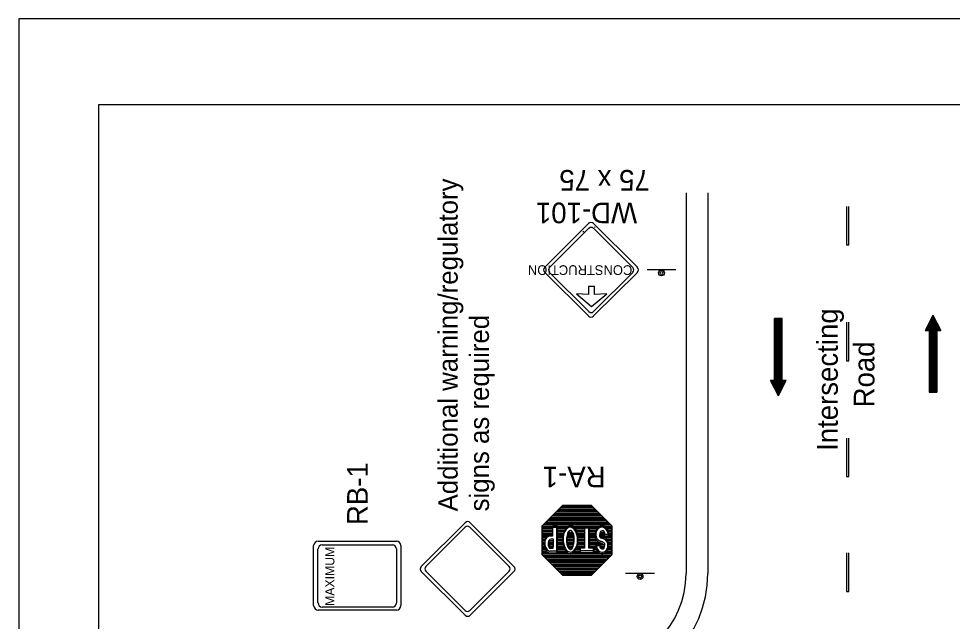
# Model space of a CAD drawing. Extents: x 1833 to 2049, y 205 to 484.
# Drawn here: x 1833.5 to 1950.4, y 408.9 to 484.4 of the extents above; entities that cross this region are included whole.
import ezdxf

# ---------------------------------------------------------------- set-up
doc = ezdxf.new("R2010")
doc.units = 0
for name, color, linetype in [('Level 10', 7, 'Continuous'), ('Level 2', 7, 'Continuous'), ('Level 44', 7, 'Continuous'), ('Level 60', 7, 'Continuous')]:
    doc.layers.add(name, color=color, linetype=linetype)

msp = doc.modelspace()

# ---------------------------------------------------------------- linework, layer by layer
at = {"layer": 'Level 10'}
for p, q in [((1917.06, 462.56), (1917.06, 414.87)), ((1919.79, 462.56), (1919.79, 414.87)), ((1928.14, 439.06), (1928.14, 446.8)), ((1929.11, 446.8), (1928.14, 446.8)), ((1928.14, 438.09), (1928.14, 446.8)), ((1928.27, 437.85), (1928.27, 446.8)), ((1928.39, 437.61), (1928.39, 446.8)), ((1928.51, 437.36), (1928.51, 446.8)), ((1928.63, 437.12), (1928.63, 446.8)), ((1928.75, 437.36), (1928.75, 446.8)), ((1928.87, 437.61), (1928.87, 446.8)), ((1928.99, 437.85), (1928.99, 446.8)), ((1929.11, 439.06), (1929.11, 446.8)), ((1929.11, 438.09), (1929.11, 446.8)), ((1947.99, 447.25), (1947.03, 445.31)), ((1947.87, 447), (1947.87, 437.57)), ((1947.99, 447.25), (1947.99, 437.57)), ((1947.99, 447.25), (1948.96, 445.31)), ((1948.11, 447), (1948.11, 437.57)), ((1947.27, 445.79), (1947.27, 445.31)), ((1947.39, 446.04), (1947.39, 445.31)), ((1947.51, 446.28), (1947.51, 437.57)), ((1947.63, 446.52), (1947.63, 437.57)), ((1947.75, 446.76), (1947.75, 437.57)), ((1948.23, 446.76), (1948.23, 437.57)), ((1948.36, 446.52), (1948.36, 437.57)), ((1948.48, 446.28), (1948.48, 437.57)), ((1948.6, 446.04), (1948.6, 445.31)), ((1948.72, 445.79), (1948.72, 445.31)), ((1947.03, 445.31), (1947.51, 445.31)), ((1947.14, 445.55), (1947.14, 445.31)), ((1947.51, 445.31), (1947.51, 437.57)), ((1948.48, 445.31), (1948.48, 437.57)), ((1948.48, 445.31), (1948.96, 445.31)), ((1948.84, 445.55), (1948.84, 445.31)), ((1928.63, 437.12), (1927.66, 439.06)), ((1928.14, 439.06), (1927.66, 439.06)), ((1927.78, 438.81), (1927.78, 439.06)), ((1927.9, 438.57), (1927.9, 439.06)), ((1928.02, 438.33), (1928.02, 439.06)), ((1928.63, 437.12), (1929.6, 439.06)), ((1929.6, 439.06), (1929.11, 439.06)), ((1929.23, 438.33), (1929.23, 439.06)), ((1929.35, 438.57), (1929.35, 439.06)), ((1929.48, 438.81), (1929.48, 439.06)), ((1947.51, 437.57), (1948.48, 437.57))]:
    msp.add_line(p, q, dxfattribs=at)
for radius in [14.52, 11.79]:
    msp.add_arc((1905.27, 414.87), radius, 270, 0, dxfattribs=at)
at = {"layer": 'Level 2'}
for p, q in [((1937.18, 460.87), (1937.18, 456.03)), ((1937.47, 456.03), (1937.47, 460.87)), ((1904.14, 457.65), (1904.24, 457.76)), ((1905.59, 458.22), (1905.69, 458.32)), ((1937.18, 456.03), (1937.47, 456.03)), ((1937.18, 446.36), (1937.18, 441.52)), ((1937.47, 441.52), (1937.47, 446.36)), ((1937.18, 441.52), (1937.47, 441.52)), ((1937.18, 431.84), (1937.18, 427.01)), ((1937.47, 427.01), (1937.47, 431.84)), ((1937.18, 427.01), (1937.47, 427.01)), ((1937.18, 417.45), (1937.18, 412.61)), ((1937.47, 412.61), (1937.47, 417.45)), ((1937.18, 412.61), (1937.47, 412.61))]:
    msp.add_line(p, q, dxfattribs=at)
at = {"layer": 'Level 44'}
for p, q in [((1904.83, 458.73), (1899.36, 453.25)), ((1910.96, 453.25), (1905.48, 458.73)), ((1899.97, 453.19), (1904.89, 458.12)), ((1905.48, 458.12), (1910.41, 453.19)), ((1910.95, 453.25), (1910.96, 453.25)), ((1915.8, 452.93), (1912.17, 452.93)), ((1899.36, 452.6), (1904.83, 447.13)), ((1904.89, 447.68), (1899.97, 452.6)), ((1905.48, 447.13), (1910.96, 452.6)), ((1910.41, 452.6), (1905.48, 447.68)), ((1905.61, 450.84), (1904.86, 450.84)), ((1904.86, 450.84), (1904.86, 449.83)), ((1905.61, 449.83), (1905.61, 450.84)), ((1904.86, 449.83), (1903.35, 449.91)), ((1903.35, 449.91), (1905.23, 448.32)), ((1905.23, 448.32), (1907.12, 449.91)), ((1907.12, 449.91), (1905.61, 449.83)), ((1901.6, 423.38), (1899.05, 420.83)), ((1905.23, 423.38), (1901.6, 423.38)), ((1907.78, 420.83), (1905.23, 423.38)), ((1889.38, 421.22), (1883.9, 415.75)), ((1895.5, 415.75), (1890.03, 421.22)), ((1884.45, 415.75), (1889.38, 420.67)), ((1889.97, 420.67), (1894.89, 415.75)), ((1899.05, 420.83), (1899.05, 417.2)), ((1900.88, 420.64), (1900.35, 420.64)), ((1900.35, 420.64), (1900.35, 419.55)), ((1900.39, 419.76), (1900.39, 420.85)), ((1900.39, 420.85), (1900.92, 420.85)), ((1900.88, 417.45), (1900.88, 420.64)), ((1900.92, 420.85), (1900.92, 417.66)), ((1904.89, 420.55), (1904.33, 420.55)), ((1904.33, 420.55), (1904.33, 418.05)), ((1904.38, 420.76), (1904.93, 420.76)), ((1904.38, 418.26), (1904.38, 420.76)), ((1904.89, 418.04), (1904.89, 420.55)), ((1904.93, 420.76), (1904.93, 418.25)), ((1907.24, 420.36), (1907.24, 420.36)), ((1907.78, 417.2), (1907.78, 420.83)), ((1870.99, 418.93), (1880.77, 418.93)), ((1900.35, 419.55), (1900.02, 419.55)), ((1900.39, 419.76), (1900.06, 419.76)), ((1900.41, 418.95), (1900.07, 418.95)), ((1900.41, 418.95), (1900.07, 418.95)), ((1900.08, 419.76), (1900.39, 419.76)), ((1900.46, 419.16), (1900.12, 419.16)), ((1900.46, 419.16), (1900.12, 419.16)), ((1900.41, 418.02), (1900.41, 418.95)), ((1900.41, 418.02), (1900.41, 418.95)), ((1900.46, 418.23), (1900.46, 419.16)), ((1900.46, 418.23), (1900.46, 419.16)), ((1907.35, 419.52), (1906.85, 419.52)), ((1907.4, 419.73), (1906.9, 419.73)), ((1870.41, 410.85), (1870.41, 418.35)), ((1870.95, 411.18), (1870.95, 417.93)), ((1871.47, 418.45), (1880.27, 418.45)), ((1880.79, 417.93), (1880.79, 411.18)), ((1881.35, 418.35), (1881.35, 410.85)), ((1900.92, 417.66), (1900.03, 417.66)), ((1900.07, 418.02), (1900.41, 418.02)), ((1900.07, 418.02), (1900.41, 418.02)), ((1900.11, 418.23), (1900.46, 418.23)), ((1900.11, 418.23), (1900.46, 418.23)), ((1902.62, 417.55), (1902.61, 417.55)), ((1902.64, 418.09), (1902.62, 418.09)), ((1904.33, 418.05), (1903.78, 418.05)), ((1903.78, 418.05), (1903.78, 417.48)), ((1903.82, 417.69), (1903.82, 418.26)), ((1903.82, 418.26), (1904.38, 418.26)), ((1905.52, 417.69), (1903.82, 417.69)), ((1905.47, 418.04), (1904.89, 418.04)), ((1904.93, 418.25), (1905.52, 418.25)), ((1905.47, 417.48), (1905.47, 418.04)), ((1905.52, 418.25), (1905.52, 417.69)), ((1905.74, 418.37), (1906.28, 418.37)), ((1905.78, 418.58), (1906.33, 418.58)), ((1899.05, 417.2), (1901.6, 414.65)), ((1899.99, 417.45), (1900.88, 417.45)), ((1903.78, 417.48), (1905.47, 417.48)), ((1905.23, 414.65), (1907.78, 417.2)), ((1871.24, 415.43), (1871.24, 415.43)), ((1883.9, 415.1), (1889.38, 409.62)), ((1883.91, 415.1), (1883.9, 415.1)), ((1889.38, 410.23), (1884.45, 415.16)), ((1894.89, 415.16), (1889.97, 410.23)), ((1890.03, 409.62), (1895.5, 415.1)), ((1901.6, 414.65), (1905.23, 414.65)), ((1913.12, 414.88), (1909.49, 414.88)), ((1880.27, 410.66), (1871.47, 410.66)), ((1880.27, 410.66), (1880.27, 410.66)), ((1881.11, 410.99), (1881.11, 410.99)), ((1880.77, 410.28), (1870.99, 410.28)), ((1880.77, 410.28), (1880.77, 410.28))]:
    msp.add_line(p, q, dxfattribs=at)
msp.add_lwpolyline([(1899.05, 420.83), (1901.6, 423.38), (1905.23, 423.38), (1907.78, 420.83), (1907.78, 417.2), (1905.23, 414.65), (1901.6, 414.65), (1899.05, 417.2)], close=True, dxfattribs=at)
for points in [[(1906.21, 422.39), (1900.61, 422.39)], [(1906.03, 422.57), (1900.79, 422.57)], [(1905.85, 422.75), (1900.97, 422.75)], [(1905.67, 422.94), (1901.15, 422.94)], [(1905.48, 423.12), (1901.34, 423.12)], [(1905.31, 423.3), (1901.52, 423.3)], [(1907.48, 421.12), (1899.34, 421.12)], [(1907.3, 421.3), (1899.52, 421.3)], [(1907.12, 421.49), (1899.7, 421.49)], [(1906.94, 421.67), (1899.88, 421.67)], [(1906.76, 421.85), (1900.07, 421.85)], [(1906.58, 422.03), (1900.25, 422.03)], [(1906.39, 422.21), (1900.43, 422.21)], [(1907.78, 420.76), (1899.05, 420.76)], [(1900.35, 420.58), (1899.05, 420.58)], [(1900.35, 420.4), (1899.05, 420.4)], [(1900.35, 420.21), (1899.05, 420.21)], [(1900.35, 420.03), (1899.05, 420.03)], [(1907.67, 420.94), (1899.16, 420.94)], [(1902.27, 420.58), (1900.88, 420.58)], [(1902.06, 420.4), (1900.88, 420.4)], [(1901.92, 420.21), (1900.88, 420.21)], [(1901.83, 420.03), (1900.88, 420.03)], [(1906.24, 420.58), (1902.85, 420.58)], [(1904.33, 420.4), (1903.06, 420.4)], [(1904.33, 420.21), (1903.19, 420.21)], [(1904.33, 420.03), (1903.29, 420.03)], [(1906, 420.4), (1904.89, 420.4)], [(1905.87, 420.21), (1904.89, 420.21)], [(1905.78, 420.03), (1904.89, 420.03)], [(1907.78, 420.58), (1906.8, 420.58)], [(1907.78, 420.4), (1907.01, 420.4)], [(1907.78, 420.21), (1907.15, 420.21)], [(1907.78, 420.03), (1907.24, 420.03)], [(1900.35, 419.85), (1899.05, 419.85)], [(1900.35, 419.67), (1899.05, 419.67)], [(1899.82, 419.49), (1899.05, 419.49)], [(1899.57, 419.31), (1899.05, 419.31)], [(1899.45, 419.13), (1899.05, 419.13)], [(1899.38, 418.94), (1899.05, 418.94)], [(1899.33, 418.76), (1899.05, 418.76)], [(1900.41, 418.76), (1899.83, 418.76)], [(1901.76, 419.85), (1900.88, 419.85)], [(1901.71, 419.67), (1900.88, 419.67)], [(1901.67, 419.49), (1900.88, 419.49)], [(1901.64, 419.31), (1900.88, 419.31)], [(1901.63, 419.13), (1900.88, 419.13)], [(1901.62, 418.94), (1900.88, 418.94)], [(1901.63, 418.76), (1900.88, 418.76)], [(1903.02, 419.13), (1902.08, 419.13)], [(1903.02, 418.94), (1902.08, 418.94)], [(1903.01, 418.76), (1902.08, 418.76)], [(1903, 419.31), (1902.1, 419.31)], [(1902.96, 419.49), (1902.13, 419.49)], [(1902.9, 419.67), (1902.19, 419.67)], [(1902.82, 419.85), (1902.28, 419.85)], [(1904.33, 419.85), (1903.35, 419.85)], [(1904.33, 419.67), (1903.4, 419.67)], [(1904.33, 419.49), (1903.43, 419.49)], [(1904.33, 419.31), (1903.45, 419.31)], [(1904.33, 418.76), (1903.46, 418.76)], [(1904.33, 419.13), (1903.47, 419.13)], [(1904.33, 418.94), (1903.47, 418.94)], [(1905.72, 419.85), (1904.89, 419.85)], [(1905.71, 419.67), (1904.89, 419.67)], [(1905.71, 419.49), (1904.89, 419.49)], [(1905.74, 419.31), (1904.89, 419.31)], [(1905.79, 419.13), (1904.89, 419.13)], [(1905.92, 418.94), (1904.89, 418.94)], [(1906.17, 418.76), (1904.89, 418.76)], [(1906.84, 419.67), (1906.22, 419.67)], [(1907.78, 419.49), (1906.24, 419.49)], [(1906.78, 419.85), (1906.27, 419.85)], [(1907.78, 419.31), (1906.43, 419.31)], [(1907.78, 419.13), (1906.86, 419.13)], [(1907.78, 418.94), (1907.09, 418.94)], [(1907.78, 418.76), (1907.21, 418.76)], [(1907.78, 419.85), (1907.3, 419.85)], [(1907.78, 419.67), (1907.33, 419.67)], [(1899.31, 418.58), (1899.05, 418.58)], [(1899.32, 418.4), (1899.05, 418.4)], [(1899.34, 418.22), (1899.05, 418.22)], [(1899.38, 418.04), (1899.05, 418.04)], [(1899.47, 417.86), (1899.05, 417.86)], [(1899.59, 417.67), (1899.05, 417.67)], [(1900.42, 418.58), (1899.77, 418.58)], [(1900.41, 418.4), (1899.78, 418.4)], [(1900.41, 418.22), (1899.82, 418.22)], [(1900.41, 418.04), (1899.99, 418.04)], [(1901.65, 418.58), (1900.88, 418.58)], [(1901.68, 418.4), (1900.88, 418.4)], [(1901.73, 418.22), (1900.88, 418.22)], [(1901.79, 418.04), (1900.88, 418.04)], [(1901.87, 417.86), (1900.88, 417.86)], [(1901.99, 417.67), (1900.88, 417.67)], [(1903, 418.58), (1902.11, 418.58)], [(1902.95, 418.4), (1902.16, 418.4)], [(1902.9, 418.22), (1902.22, 418.22)], [(1902.81, 418.04), (1902.3, 418.04)], [(1903.78, 417.67), (1903.1, 417.67)], [(1903.78, 417.86), (1903.22, 417.86)], [(1903.78, 418.04), (1903.3, 418.04)], [(1904.33, 418.22), (1903.37, 418.22)], [(1904.33, 418.4), (1903.41, 418.4)], [(1904.33, 418.58), (1903.44, 418.58)], [(1906.58, 418.58), (1904.89, 418.58)], [(1906.81, 418.4), (1904.89, 418.4)], [(1905.74, 418.22), (1904.89, 418.22)], [(1905.79, 418.04), (1905.47, 418.04)], [(1905.84, 417.86), (1905.47, 417.86)], [(1905.94, 417.67), (1905.47, 417.67)], [(1906.84, 418.22), (1906.27, 418.22)], [(1906.76, 418.04), (1906.35, 418.04)], [(1907.78, 417.67), (1907.08, 417.67)], [(1907.78, 417.86), (1907.19, 417.86)], [(1907.78, 418.04), (1907.24, 418.04)], [(1907.78, 418.58), (1907.26, 418.58)], [(1907.78, 418.22), (1907.27, 418.22)], [(1907.78, 418.4), (1907.28, 418.4)], [(1899.82, 417.49), (1899.05, 417.49)], [(1907.78, 417.31), (1899.05, 417.31)], [(1907.7, 417.13), (1899.12, 417.13)], [(1907.52, 416.95), (1899.3, 416.95)], [(1907.34, 416.77), (1899.49, 416.77)], [(1907.16, 416.59), (1899.67, 416.59)], [(1906.98, 416.4), (1899.85, 416.4)], [(1902.16, 417.49), (1900.88, 417.49)], [(1903.78, 417.49), (1902.93, 417.49)], [(1906.1, 417.49), (1905.47, 417.49)], [(1907.78, 417.49), (1906.93, 417.49)], [(1906.8, 416.22), (1900.03, 416.22)], [(1906.61, 416.04), (1900.21, 416.04)], [(1906.43, 415.86), (1900.39, 415.86)], [(1906.25, 415.68), (1900.57, 415.68)], [(1906.07, 415.5), (1900.76, 415.5)], [(1905.89, 415.31), (1900.94, 415.31)], [(1905.71, 415.13), (1901.12, 415.13)], [(1905.53, 414.95), (1901.31, 414.95)], [(1905.34, 414.77), (1901.48, 414.77)]]:
    msp.add_lwpolyline(points, dxfattribs=at)
for centre, radius in [((1913.98, 452.52), 0.363), ((1913.98, 452.52), 0.181), ((1911.3, 414.47), 0.363), ((1911.3, 414.47), 0.181)]:
    msp.add_circle(centre, radius, dxfattribs=at)
for centre, radius, start, end in [((1905.15, 458.4), 0.458, 45, 135), ((1905.19, 457.82), 0.412, 45, 135), ((1899.68, 452.92), 0.458, 135, 225), ((1900.26, 452.9), 0.412, 135, 225), ((1910.11, 452.9), 0.412, 315, 45), ((1910.63, 452.92), 0.458, 315, 45), ((1905.15, 447.45), 0.458, 225, 315), ((1905.19, 447.97), 0.412, 225, 315), ((1889.71, 420.9), 0.458, 45, 135), ((1889.67, 420.38), 0.412, 45, 135), ((1907.63, 419.59), 1.92, 171.247, 183.9864), ((1907.18, 419.46), 1.51, 145.5092, 163.2894), ((1907.68, 419.8), 1.92, 171.247, 183.9864), ((1907.23, 419.67), 1.51, 145.5092, 163.2894), ((1906.65, 419.82), 0.868, 113.1413, 144.9906), ((1906.69, 420.03), 0.868, 113.1413, 144.9906), ((1906.68, 419.67), 0.459, 146.253, 178.7323), ((1906.73, 419.88), 0.459, 146.253, 178.7323), ((1906.62, 419.84), 0.355, 172.5761, 210.4776), ((1906.53, 419.66), 0.345, 95.4374, 134.0626), ((1906.52, 420.11), 0.544, 52.0536, 112.7397), ((1906.58, 419.87), 0.345, 95.4374, 134.0626), ((1906.56, 420.32), 0.544, 52.0536, 112.7397), ((1906.51, 419.63), 0.372, 50.6966, 91.4573), ((1906.55, 419.85), 0.372, 50.6966, 91.4573), ((1906.46, 419.67), 0.382, 6.8728, 42.7449), ((1906.5, 419.88), 0.382, 6.8728, 42.7449), ((1906.15, 419.58), 1.19, 28.4154, 53.6553), ((1906.14, 419.74), 0.761, 359.0172, 13.5172), ((1906.19, 419.79), 1.19, 28.4154, 53.6553), ((1905.68, 419.44), 1.67, 2.3841, 24.9519), ((1905.73, 419.65), 1.67, 2.3841, 24.9519), ((1870.99, 418.35), 0.579, 90, 180), ((1880.77, 418.35), 0.579, 360, 90), ((1900.66, 418.51), 1.35, 169.7521, 182.7916), ((1900.66, 418.51), 1.35, 169.7521, 182.7916), ((1901.06, 418.4), 1.76, 158.3153, 168.6699), ((1900.7, 418.72), 1.35, 169.7521, 182.7916), ((1900.7, 418.72), 1.35, 169.7521, 182.7916), ((1901.11, 418.61), 1.76, 158.3153, 168.6699), ((1900.22, 418.74), 0.86, 138.2922, 158.6031), ((1900.22, 418.74), 0.86, 138.2922, 158.6031), ((1900.27, 418.95), 0.86, 138.2922, 158.6031), ((1900.27, 418.95), 0.86, 138.2922, 158.6031), ((1900, 418.99), 0.531, 115.3838, 142.6188), ((1900.04, 419.2), 0.531, 115.3838, 142.6188), ((1900.16, 418.78), 0.784, 106.602, 119.8091), ((1900.24, 418.54), 0.464, 146.5086, 177.0313), ((1900.24, 418.54), 0.464, 146.5086, 177.0313), ((1900.2, 419), 0.784, 106.602, 119.8091), ((1900.33, 418.69), 0.52, 170.3417, 195.2342), ((1900.33, 418.69), 0.52, 170.3417, 195.2342), ((1900.28, 418.76), 0.464, 146.5086, 177.0313), ((1900.28, 418.76), 0.464, 146.5086, 177.0313), ((1900.15, 418.6), 0.361, 101.9191, 145.7868), ((1900.15, 418.6), 0.361, 101.9191, 145.7868), ((1900.19, 418.81), 0.361, 101.9191, 145.7868), ((1900.19, 418.81), 0.361, 101.9191, 145.7868), ((1900, 419.36), 0.184, 79.7909, 113.5419), ((1900.04, 419.58), 0.184, 79.7909, 113.5419), ((1907.06, 419.6), 1.36, 185.9097, 201.9865), ((1907.11, 419.81), 1.36, 185.9097, 201.9865), ((1904.16, 417.5), 2.28, 39.479, 43.426), ((1904.21, 417.71), 2.28, 39.479, 43.426), ((1906.83, 419.89), 1.31, 226.2465, 247.9263), ((1906.87, 420.1), 1.31, 226.2465, 247.9263), ((1906.58, 419.62), 0.355, 172.5761, 210.4776), ((1906.59, 419.66), 0.387, 214.2083, 254.1552), ((1906.63, 419.88), 0.387, 214.2083, 254.1552), ((1905.78, 417.12), 1.87, 57.9816, 70.979), ((1904.27, 413.57), 6.13, 64.4624, 68.8312), ((1904.32, 413.78), 6.13, 64.4624, 68.8312), ((1906.1, 419.53), 0.761, 359.0172, 13.5172), ((1906.44, 418.41), 0.847, 20.4481, 55.1107), ((1906.49, 418.62), 0.847, 20.4481, 55.1107), ((1906.14, 418.58), 1.19, 354.8171, 15.9183), ((1871.48, 417.93), 0.521, 90, 180), ((1880.27, 417.93), 0.521, 360, 90), ((1900.99, 418.54), 1.68, 183.3903, 195.6597), ((1901.03, 418.75), 1.68, 183.3903, 195.6597), ((1900.21, 418.29), 0.864, 193.0674, 213.762), ((1900.26, 418.5), 0.864, 193.0674, 213.762), ((1900.2, 418.21), 0.814, 209.2241, 228.5308), ((1900.2, 418.21), 0.814, 209.2241, 228.5308), ((1900.25, 418.42), 0.814, 209.2241, 228.5308), ((1900.25, 418.42), 0.814, 209.2241, 228.5308), ((1900.03, 417.97), 0.53, 224.8528, 265.0441), ((1900.08, 418.18), 0.53, 224.8528, 265.0441), ((1900.29, 418.48), 0.52, 170.3417, 195.2342), ((1900.29, 418.48), 0.52, 170.3417, 195.2342), ((1900.27, 418.42), 0.489, 188.6031, 214.217), ((1900.27, 418.42), 0.489, 188.6031, 214.217), ((1900.31, 418.63), 0.489, 188.6031, 214.217), ((1900.31, 418.63), 0.489, 188.6031, 214.217), ((1900.12, 418.32), 0.315, 215.1198, 259.3117), ((1900.12, 418.32), 0.315, 215.1198, 259.3117), ((1900.17, 418.53), 0.315, 215.1198, 259.3117), ((1900.17, 418.53), 0.315, 215.1198, 259.3117), ((1907.12, 418.39), 1.38, 180.6952, 197.1452), ((1907.16, 418.61), 1.38, 180.6952, 197.1452), ((1906.77, 418.24), 0.998, 194.564, 229.0063), ((1906.81, 418.45), 0.998, 194.564, 229.0063), ((1906.56, 418.12), 0.591, 226.1369, 301.3987), ((1906.71, 418.3), 0.449, 170.4412, 219.3244), ((1906.76, 418.51), 0.449, 170.4412, 219.3244), ((1905.73, 416.91), 1.87, 57.9816, 70.979), ((1906.57, 418.25), 0.308, 227.3017, 289.0119), ((1906.61, 418.46), 0.308, 227.3017, 289.0119), ((1906.55, 418.23), 0.294, 293.8064, 352.2407), ((1906.59, 418.44), 0.294, 293.8064, 352.2407), ((1906.58, 418.27), 0.268, 344.131, 58.1476), ((1906.63, 418.48), 0.268, 344.131, 58.1476), ((1906.3, 418.22), 0.967, 303.3662, 335.6734), ((1906.34, 418.43), 0.967, 303.3662, 335.6734), ((1905.92, 418.33), 1.35, 337.7332, 357.1392), ((1905.97, 418.54), 1.35, 337.7332, 357.1392), ((1906.09, 418.37), 1.19, 354.8171, 15.9183), ((1906.52, 417.91), 0.591, 226.1369, 301.3987), ((1884.23, 415.42), 0.458, 135, 225), ((1884.75, 415.45), 0.412, 135, 225), ((1894.6, 415.45), 0.412, 315, 45), ((1895.18, 415.42), 0.458, 315, 45), ((1870.99, 410.85), 0.579, 180, 270), ((1871.48, 411.18), 0.521, 180, 270), ((1880.27, 411.18), 0.521, 270, 360), ((1880.77, 410.85), 0.579, 270, 360), ((1889.67, 410.53), 0.412, 225, 315), ((1889.71, 409.95), 0.458, 225, 315)]:
    msp.add_arc(centre, radius, start, end, dxfattribs=at)
for centre, major_axis, ratio, start_param, end_param in [((1902.59, 419.21), (0.01, 1.66), 0.558644, 0.656861, 3.168126), ((1902.55, 419), (0.01, 1.66), 0.558644, 3.185857, 9.451311), ((1902.59, 419.21), (0.01, 1.66), 0.558644, 4.129576, 6.939747), ((1902.55, 418.96), (-0.01, 1.09), 0.432619, 3.239639, 9.473919), ((1902.59, 419.17), (-0.01, 1.09), 0.432619, 3.890436, 7.165085), ((1902.59, 419.17), (-0.01, 1.09), 0.432619, 0.881967, 3.190734), ((1902.59, 419.21), (0.01, 1.66), 0.558644, 3.185857, 4.129398), ((1902.59, 419.17), (-0.01, 1.09), 0.432619, 3.239639, 3.888884)]:
    msp.add_ellipse(centre, major_axis=major_axis, ratio=ratio, start_param=start_param, end_param=end_param, dxfattribs=at)
at = {"layer": 'Level 60'}
for points in [[(2049.46, 484.39), (1833.46, 484.39), (1833.46, 205.39), (2049.46, 205.39)], [(2030.33, 473.58), (1843.46, 473.58), (1843.46, 216.2), (2030.33, 216.2)]]:
    msp.add_lwpolyline(points, close=True, dxfattribs=at)

# ---------------------------------------------------------------- texts
at = {"layer": 'Level 10'}
for s, height, rotation, p in [('Additional warning/regulatory', 2.419, 90, (1888.45, 422.64)), ('75 x 75', 2.585, 180, (1912.52, 465.43)), ('WD-101', 2.585, 180, (1910.93, 461.34)), ('signs as required', 2.419, 90, (1892.37, 422.64)), ('Intersecting', 2.585, 90, (1936.07, 430.22)), ('Road', 2.585, 90, (1940.66, 435.68)), ('RB-1', 2.585, 90, (1877.19, 420.93)), ('RA-1', 2.585, 180, (1906.99, 428.25))]:
    msp.add_text(s, height=height, rotation=rotation, dxfattribs=at).set_placement(p)
at = {"layer": 'Level 44'}
for s, height, rotation, p in [('CONSTRUCTION', 1.2148, 180, (1910.33, 453.49)), ('MAXIMUM', 1.147, 90, (1873.01, 410.8))]:
    msp.add_text(s, height=height, rotation=rotation, dxfattribs=at).set_placement(p)

doc.saveas('drawing.dxf')
